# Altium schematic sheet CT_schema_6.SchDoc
size 254 x 194 mm
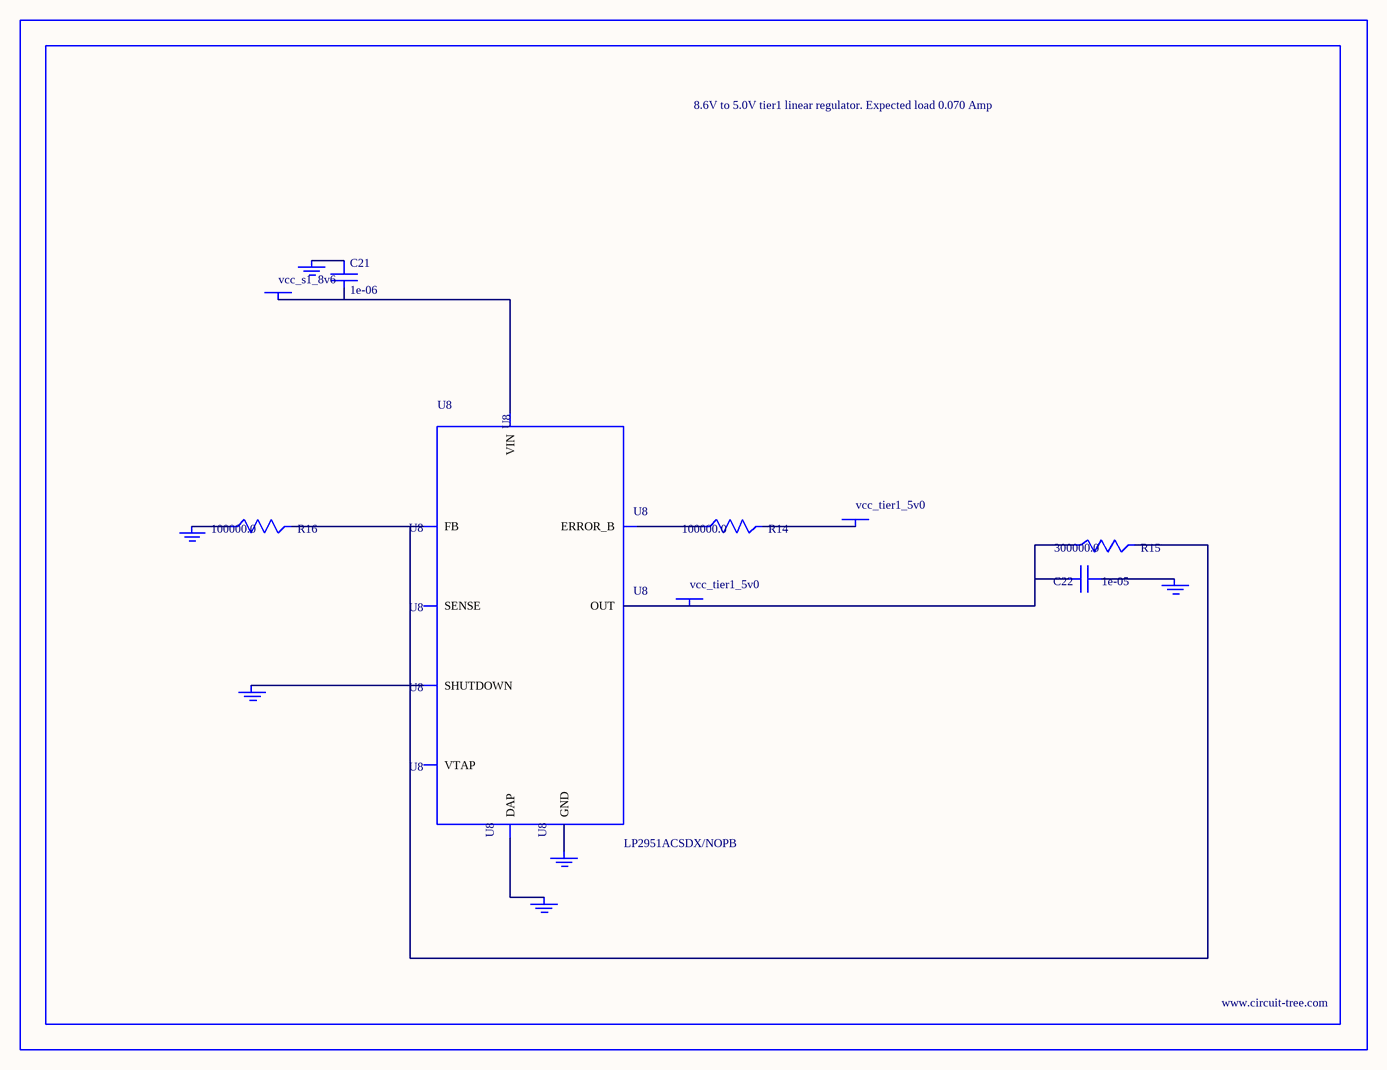
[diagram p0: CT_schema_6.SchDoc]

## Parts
BORDER5  (no value)
C21  1e-06  [C0603]
C22  1e-05  [C1210]
GND_INSTANCE_5_0  (no value)
GND_INSTANCE_5_1  (no value)
GND_INSTANCE_5_2  (no value)
GND_INSTANCE_5_3  (no value)
GND_INSTANCE_5_4  (no value)
GND_INSTANCE_5_5  (no value)
POWER_INSTANCE_5_0  vcc_tier1_5v0
POWER_INSTANCE_5_1  vcc_s1_8v6
POWER_INSTANCE_5_2  vcc_tier1_5v0
R14  100000.0  [R0603]
R15  300000.0  [R0603]
R16  100000.0  [R0603]
U8  LP2951ACSDX/NOPB  [WSON-8]

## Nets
NetC21_1: C21.1 GND_INSTANCE_5_3.0(GND)
NetC21_2: C21.2 POWER_INSTANCE_5_1.0(PWR) U8.8(VIN)
NetC22_1: C22.1 GND_INSTANCE_5_0.0(GND)
NetC22_2: C22.2 POWER_INSTANCE_5_2.0(PWR) R15.1 U8.1(OUT)
NetGND_INSTANCE_5_1_0: GND_INSTANCE_5_1.0(GND) U8.3(SHUTDOWN)
NetGND_INSTANCE_5_2_0: GND_INSTANCE_5_2.0(GND) R16.1
NetGND_INSTANCE_5_4_0: GND_INSTANCE_5_4.0(GND) U8.PAD(DAP)
NetGND_INSTANCE_5_5_0: GND_INSTANCE_5_5.0(GND) U8.4(GND)
NetPOWER_INSTANCE_5_0_0: POWER_INSTANCE_5_0.0(PWR) R14.2
NetR14_1: R14.1 U8.5(ERROR_B)
NetR15_2: R15.2 R16.2 U8.7(FB)

Not connected (* = marked no-connect by the designer): U8 2(SENSE) 6(VTAP)

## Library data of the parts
BORDER5 = BORDER_PAGE5
C21 = C0603C105K3RACTU
C22 = GRM32DR61E106MA12L
GND_INSTANCE_5_0-GND_INSTANCE_5_5 = GND
POWER_INSTANCE_5_0-POWER_INSTANCE_5_2 = PWR
R14 R16 = RC0603JR-07100KL
R15 = RC0603JR-07300KL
